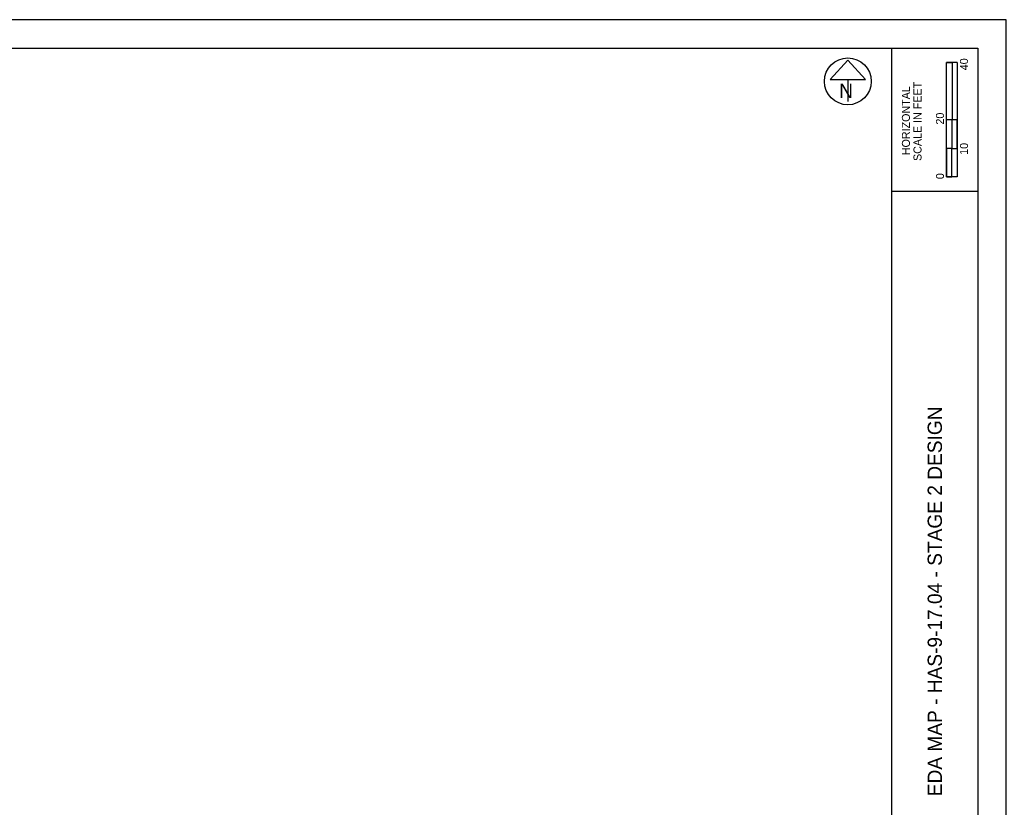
# Model space of a CAD drawing. Extents: x 2380994 to 2382560, y 256585 to 258122.
# Drawn here: x 2382214.9 to 2382560, y 257846.8 to 258122.3 of the extents above; entities that cross this region are included whole.
import ezdxf

# ---------------------------------------------------------------- set-up
doc = ezdxf.new("R2010")
doc.units = 0
for name, color, linetype in [('PM_X_Edge_Line', 7, 'Continuous'), ('RW_X_CL', 7, 'Continuous'), ('SC_Scratch20', 7, 'Continuous'), ('SC_Scratch4', 7, 'Continuous'), ('SC_Scratch5', 7, 'Continuous')]:
    doc.layers.add(name, color=color, linetype=linetype)

msp = doc.modelspace()

# ---------------------------------------------------------------- linework, layer by layer
at = {"layer": 'PM_X_Edge_Line'}
msp.add_lwpolyline([(2381880.03, 257682.34), (2382560.03, 257682.34), (2382560.03, 258122.34), (2381880.03, 258122.34)], close=True, dxfattribs=at)
at = {"layer": 'RW_X_CL'}
for p, q in [((2382539.16, 258067.34), (2382539.16, 258107.34)), ((2382542.91, 258107.34), (2382539.16, 258107.34)), ((2382539.16, 258087.34), (2382539.16, 258107.34)), ((2382539.16, 258107.34), (2382541.03, 258107.34)), ((2382541.03, 258107.34), (2382541.05, 258107.34)), ((2382541.05, 258107.34), (2382541.05, 258087.34)), ((2382542.91, 258107.34), (2382542.91, 258067.34)), ((2382541.05, 258087.34), (2382539.16, 258087.34)), ((2382542.9, 258087.34), (2382541.03, 258087.34)), ((2382541.03, 258087.34), (2382541.03, 258077.34)), ((2382542.9, 258077.34), (2382542.9, 258087.34)), ((2382541.03, 258077.34), (2382539.16, 258077.34)), ((2382539.16, 258077.34), (2382539.16, 258067.34)), ((2382541.03, 258077.34), (2382542.9, 258077.34)), ((2382541.03, 258067.34), (2382541.03, 258077.34)), ((2382542.91, 258067.34), (2382539.16, 258067.34)), ((2382539.16, 258067.34), (2382541.03, 258067.34))]:
    msp.add_line(p, q, dxfattribs=at)
at = {"layer": 'SC_Scratch20'}
msp.add_circle((2382504.62, 258100.77), 8.2, dxfattribs=at)
at = {"layer": 'SC_Scratch4'}
for p, q in [((2382504.62, 258108.24), (2382498.47, 258101.42)), ((2382510.77, 258101.42), (2382504.62, 258108.24)), ((2382498.47, 258101.42), (2382510.77, 258101.42)), ((2382504.62, 258101.42), (2382504.62, 258093.68))]:
    msp.add_line(p, q, dxfattribs=at)
msp.add_circle((2382504.62, 258100.77), 8.2, dxfattribs=at)
at = {"layer": 'SC_Scratch5'}
for p, q in [((2382520.03, 257692.34), (2382520.03, 258112.34)), ((2382520.03, 258062.34), (2382550.03, 258062.34))]:
    msp.add_line(p, q, dxfattribs=at)
msp.add_lwpolyline([(2381910.03, 258112.34), (2382550.03, 258112.34), (2382550.03, 257692.34), (2381910.03, 257692.34)], close=True, dxfattribs=at)

# ---------------------------------------------------------------- texts
at = {"layer": 'RW_X_CL'}
for s, height, p in [('40', 2.8, (2382546.64, 258104.67)), ('SCALE IN FEET', 2.8, (2382530.38, 258072.92)), ('HORIZONTAL', 2.8, (2382526.33, 258074.95)), ('20', 2.8, (2382538.24, 258085.67)), ('10', 2.8, (2382546.64, 258075.07)), ('0', 2.8, (2382538.24, 258066.57)), ('EDA MAP - HAS-9-17.04 - STAGE 2 DESIGN', 5, (2382537.53, 257850.67))]:
    msp.add_text(s, height=height, rotation=90, dxfattribs=at).set_placement(p)
at = {"layer": 'SC_Scratch4'}
msp.add_text('N', height=5, dxfattribs=at).set_placement((2382501.6, 258094.94))

doc.saveas('drawing.dxf')
